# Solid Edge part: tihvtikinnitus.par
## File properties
Author: Argo
Template: Normal.par
Last saved by: Argo
Revision: 7
Application: Solid Edge
Material: Aluminum, 3004
Face Style: Aluminum
Fill Style: ANSI38(Aluminum)
Virtual Style: Polished aluminum
Coef. of Thermal Exp: 2.3e-05
Thermal Conductivity: 170.0
Specific Heat: 920.0
Modulus of Elasticity: 68947570000.0
Poission's Ratio: 0.33
Yield Stress: 68947570.0
Ultimate Stress: 179263682.0
Elongation: 0.0
Density: 2712,000 kg/m^3
Accuracy: 0,990
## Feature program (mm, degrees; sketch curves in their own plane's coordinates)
sketch for "unnamed Protrusion 1" plane through (0, 0, 0) normal (0, 0, 1) x-axis (1, 0, 0)
  circle centre (0, 0) radius 1.5
extrude "unnamed Protrusion 1" add finite 1 along +normal
sketch for "unnamed Cutout 1" plane through (0, 0, 1) normal (0, 0, 1) x-axis (1, 0, 0)
  circle centre (0, 0) radius 1
extrude "unnamed Cutout 1" cut to key point along -normal
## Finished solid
Body 1: solid body, 4 faces, 4 edges, 0 vertices.
  Faces by surface: cylinder 2, plane 2
  Edges by curve: circle 4
Bounding box of the edges (mm): 3.000 x 3.000 x 1.000, from (-1.5, -1.5, 0) to (1.5, 1.5, 1).
Cylindrical faces by radius (mm): R1 x1, R1.5 x1
Planar faces by outward normal: +z 1, -z 1
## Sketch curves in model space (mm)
circle centre (0, 0, 1) radius 1
circle centre (0, 0, 0) radius 1.5
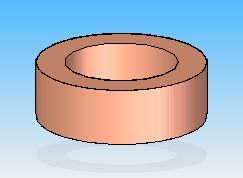
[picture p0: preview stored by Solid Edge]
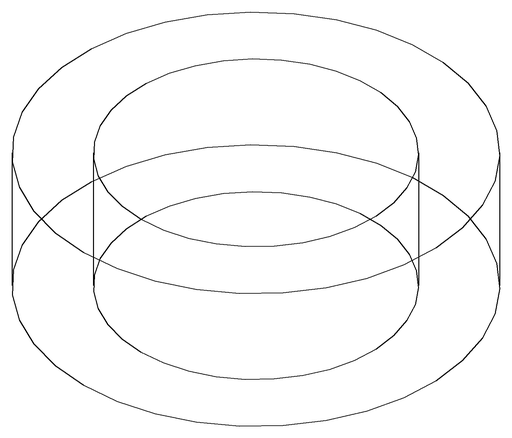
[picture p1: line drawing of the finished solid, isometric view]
